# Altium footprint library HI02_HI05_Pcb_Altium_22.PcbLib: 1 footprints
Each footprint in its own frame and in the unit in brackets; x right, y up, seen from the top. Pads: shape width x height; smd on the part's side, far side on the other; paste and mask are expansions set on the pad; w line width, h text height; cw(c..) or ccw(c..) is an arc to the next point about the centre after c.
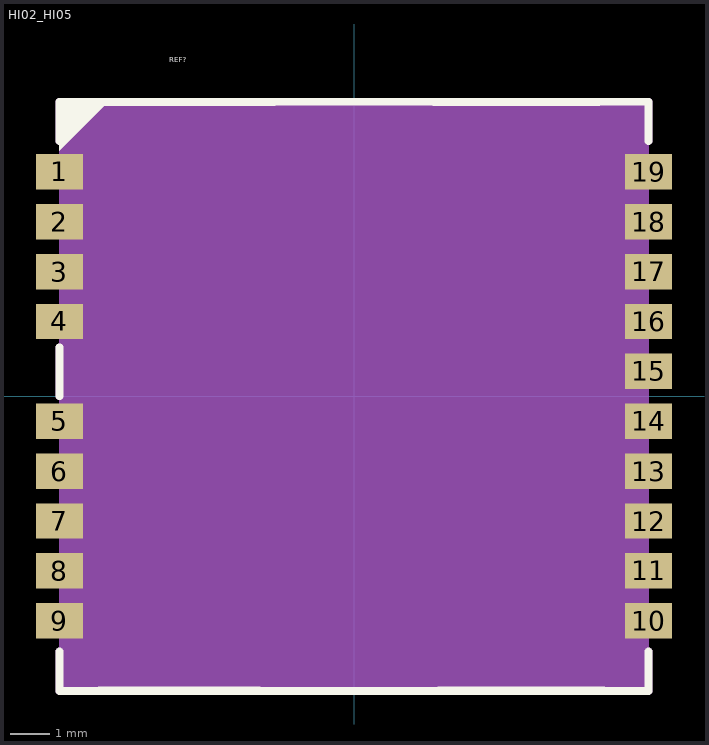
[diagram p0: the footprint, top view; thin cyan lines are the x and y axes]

## HI02_HI05 [mm]
pads (19):
  rect 1.2x0.9 smd: 1(-7.5,5.715) 2(-7.5,4.445) 3(-7.5,3.175) 4(-7.5,1.905) 5(-7.5,-0.635) 6(-7.5,-1.905) 7(-7.5,-3.175) 8(-7.5,-4.445) 9(-7.5,-5.715) 10(7.5,-5.715) 11(7.5,-4.445) 12(7.5,-3.175) 13(7.5,-1.905) 14(7.5,-0.635) 15(7.5,0.635) 16(7.5,1.905) 17(7.5,3.175) 18(7.5,4.445) 19(7.5,5.715)
Top Overlay:
  dashed: -6.25,7.5 -7.5,6.25 -7.5,7.5
  lines w0.2: -7.5,-6.5 -7.5,-7.5 7.5,-7.5 7.5,-6.5 ; -7.5,0 -7.5,1.25 ; -7.5,6.5 -7.5,7.5 7.5,7.5 7.5,6.5 ; -6.477,-7.493 -2.413,-7.493 ; -6.35,7.493 -2.032,7.493 ; 2.032,7.493 6.223,7.493 ; 2.159,-7.493 6.35,-7.493
  text "REF?" at -4.699,8.509 h0.13
PIN_NUMBER:
  text "5" at -7.736,-0.635 h0.13
  text "11" at 0.533,-6.7 h0.13
  text "1" at -7.736,5.715 h0.13
  text "4" at -7.736,1.905 h0.13
  text "22" at -0.737,6.7 h0.13
  text "9" at -7.736,-5.715 h0.13
  text "14" at 8.345,-0.635 h0.13
  text "11" at 8.345,-4.445 h0.13
  text "10" at -0.737,-6.7 h0.13
  text "19" at 8.345,5.715 h0.13
  text "18" at 8.345,4.445 h0.13
  text "2" at -7.736,4.445 h0.13
  text "8" at -7.736,-4.445 h0.13
  text "13" at 8.345,-1.905 h0.13
  text "3" at -7.736,3.175 h0.13
  text "7" at -7.736,-3.175 h0.13
  text "21" at 0.533,6.7 h0.13
  text "6" at -7.736,-1.905 h0.13
  text "17" at 8.345,3.175 h0.13
  text "16" at 8.345,1.905 h0.13
  text "12" at 8.345,-3.175 h0.13
  text "10" at 8.345,-5.715 h0.13
ASSEMBLY_TOP:
  lines w0.2: -7.5,-6.5 -7.5,-7.5 7.5,-7.5 7.5,-6.5 ; -7.5,0 -7.5,1.25 ; -7.5,6.5 -7.5,7.5 7.5,7.5 7.5,6.5
PLACE_BOUND_TOP:
  region: 7.5,-7.5 7.5,7.5 -7.5,7.5 -7.5,-7.5
DRAWING_ORIGIN:
  lines w0.025: -0.635,0 0.635,0 ; 0,-0.635 0,0.635
3D body: height 3.81, standoff 0, extent -7.5,-7.5 7.5,7.5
